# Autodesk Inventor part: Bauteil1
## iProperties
Shininess: 64.0
Length Units: 11269
Angle Units: 11279
Time Units: 11290
Mass Units: 11283
Length Display Precision: 3
Angle Display Precision: 2
Compacted: True
Part Number: Bauteil1
Document SubType Name: Modeling
Created: 2003-11
Material: Standard
Designer: HJ
Manufacturer: Standard
Standards Organization: Custom
Density: 0.0
Volumn: 0.0
Area: 0.0
PropertySet Name: Model Information
Control State: 0
Master: False
Checked Out: False
Author: HJ
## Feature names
1. Extrusion1
